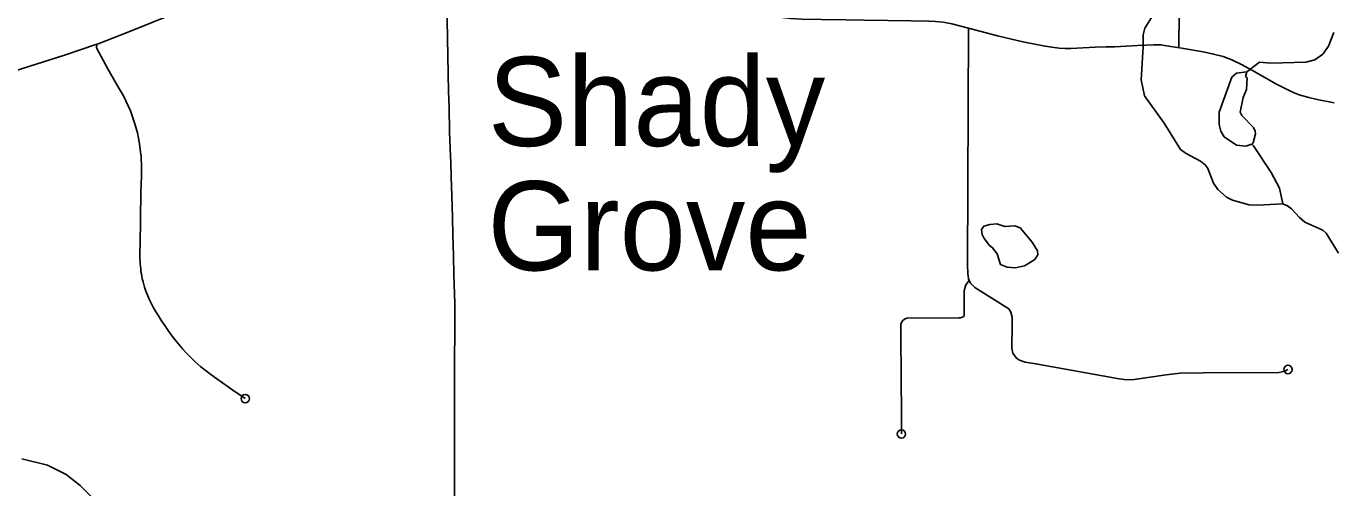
# Model space of a CAD drawing. Extents: x -19 to 366, y -4 to 359.
# Drawn here: x 143.314 to 144.78, y 191.501 to 192.02 of the extents above; entities that cross this region are included whole.
import ezdxf

# ---------------------------------------------------------------- set-up
doc = ezdxf.new("R2010")
doc.units = 0
for name, color, linetype in [('R_Horz Alg Annot', 7, 'Continuous'), ('R_ROW', 7, 'Continuous'), ('R_ROW Annot', 7, 'Continuous'), ('R_Temp Easement', 7, 'Continuous'), ('Sheet Fence', 7, 'Continuous')]:
    doc.layers.add(name, color=color, linetype=linetype)

msp = doc.modelspace()

# ---------------------------------------------------------------- linework, layer by layer
at = {"layer": 'R_ROW'}
for points in [[(143.785, 192.1059), (143.7855, 192.0918), (143.7865, 192.0521), (143.7867, 192.0267), (143.7881, 191.9466), (143.7888, 191.9291), (143.7894, 191.901)], [(143.4977, 192.041), (143.4828, 192.0352), (143.4289, 192.0136), (143.3943, 192.0002), (143.3929, 191.9996)], [(144.3723, 192.0176), (144.3536, 192.0224), (144.3441, 192.0243), (144.3355, 192.0253), (144.3281, 192.0257), (144.3077, 192.0261), (144.2556, 192.0267), (144.235, 192.0272), (144.2071, 192.0276), (144.1852, 192.0279), (144.1726, 192.0287), (144.1597, 192.0301), (144.1385, 192.0339), (144.126, 192.0374), (144.1074, 192.0433)], [(144.3723, 192.0176), (144.3714, 191.7521), (144.3715, 191.7421)], [(144.7833, 191.9338), (144.7642, 191.9375), (144.755, 191.9397), (144.7441, 191.9428), (144.7384, 191.9451), (144.7321, 191.948), (144.7186, 191.9549), (144.6915, 191.9702), (144.6833, 191.9747), (144.6799, 191.9765), (144.6682, 191.9822), (144.6585, 191.9857), (144.6478, 191.9885), (144.6379, 191.9908), (144.6143, 191.9947), (144.6071, 191.996), (144.5948, 191.998), (144.5885, 191.9989), (144.5803, 191.999), (144.5622, 191.9984), (144.5368, 191.9969), (144.527, 191.9967), (144.5149, 191.9963), (144.4873, 191.9949), (144.4811, 191.9949), (144.4743, 191.9953), (144.4659, 191.9962), (144.4584, 191.9974), (144.4353, 192.002), (144.4208, 192.0052), (144.4051, 192.009), (144.3723, 192.0176)], [(143.3929, 191.9996), (143.3568, 191.9872), (143.236, 191.9493)], [(143.3929, 191.9996), (143.3927, 191.9957), (143.4058, 191.9714), (143.4163, 191.9529), (143.4228, 191.9418), (143.4307, 191.9247), (143.4351, 191.9126), (143.4369, 191.9065), (143.4385, 191.9003), (143.4398, 191.8941), (143.4409, 191.8879), (143.4426, 191.8756), (143.4427, 191.8752), (143.4429, 191.8701), (143.443, 191.8649), (143.443, 191.8594), (143.443, 191.8519), (143.4428, 191.8421), (143.4426, 191.8331), (143.4415, 191.7741), (143.4414, 191.7669), (143.4414, 191.7611), (143.4414, 191.7581), (143.4415, 191.7558), (143.4417, 191.7526), (143.4419, 191.7505), (143.4423, 191.7474), (143.4426, 191.7445), (143.4431, 191.7418), (143.4436, 191.7384), (143.4441, 191.7364), (143.4449, 191.733), (143.4459, 191.7297), (143.4466, 191.727), (143.4482, 191.7223), (143.4502, 191.717), (143.4522, 191.7125), (143.4543, 191.708), (143.4566, 191.7037), (143.4588, 191.6999), (143.4622, 191.6946), (143.4658, 191.6892), (143.4695, 191.6837), (143.474, 191.6771), (143.4778, 191.6719), (143.4822, 191.6662), (143.4857, 191.6618), (143.4897, 191.6572), (143.4939, 191.6527), (143.4986, 191.6479), (143.5036, 191.6431), (143.5099, 191.6375), (143.5148, 191.6336), (143.521, 191.6289), (143.5279, 191.624), (143.5343, 191.6195), (143.5407, 191.615), (143.5458, 191.6114), (143.5598, 191.6017)], [(143.7894, 191.901), (143.7905, 191.8739), (143.7908, 191.8667), (143.7913, 191.8507), (143.7917, 191.8294), (143.7925, 191.8055), (143.7931, 191.7853), (143.7938, 191.7619), (143.7943, 191.7412), (143.7951, 191.7084), (143.7952, 191.673), (143.795, 191.6492), (143.7948, 191.6158), (143.7948, 191.6002), (143.7948, 191.5857), (143.7948, 191.5603), (143.7948, 191.5467), (143.7948, 191.4948), (143.7948, 191.4924)], [(144.3715, 191.7421), (144.3724, 191.7364), (144.3747, 191.7313), (144.3796, 191.7266), (144.4149, 191.7045), (144.4177, 191.7024), (144.4199, 191.6989), (144.4213, 191.6933), (144.4214, 191.6847), (144.4212, 191.6582), (144.4223, 191.6526), (144.4262, 191.647), (144.4296, 191.6448), (144.436, 191.6428), (144.4481, 191.6409), (144.5418, 191.6238), (144.5505, 191.6229), (144.5584, 191.6232), (144.5766, 191.6257), (144.5945, 191.6285), (144.6102, 191.6302), (144.6362, 191.6308), (144.7213, 191.6311), (144.728, 191.6325), (144.7314, 191.6344)], [(144.3733, 191.7343), (144.3694, 191.7294), (144.3676, 191.7228), (144.3676, 191.6988), (144.3676, 191.6961), (144.367, 191.6937), (144.3654, 191.6931), (144.3633, 191.6925), (144.3615, 191.6925), (144.3031, 191.6919), (144.3004, 191.691), (144.2983, 191.6892), (144.2964, 191.6858), (144.2964, 191.6816), (144.2964, 191.6719), (144.2973, 191.582), (144.297, 191.562)]]:
    msp.add_lwpolyline(points, dxfattribs=at)
for centre in [(144.7314, 191.6344), (143.5598, 191.6017), (144.297, 191.562)]:
    msp.add_circle(centre, 0.00473, dxfattribs=at)
at = {"layer": 'R_ROW Annot'}
msp.add_lwpolyline([(144.6088, 191.9957), (144.6097, 192.1166)], dxfattribs=at)
at = {"layer": 'R_Temp Easement'}
for points in [[(144.5922, 191.9109), (144.5702, 191.9416), (144.5666, 191.9598), (144.5687, 191.9968), (144.5688, 192.0102), (144.5704, 192.0177), (144.5798, 192.0325)], [(144.6853, 191.9687), (144.6994, 191.9795), (144.7121, 191.9784), (144.7515, 191.9795), (144.7617, 191.9823), (144.7704, 191.9886), (144.7771, 191.9976), (144.7829, 192.0128)], [(144.6906, 191.8874), (144.6921, 191.8889), (144.6948, 191.899), (144.6946, 191.9022), (144.6927, 191.9062), (144.6795, 191.9198), (144.6777, 191.9233), (144.681, 191.9397), (144.6847, 191.949), (144.6854, 191.9619), (144.6838, 191.9636), (144.6853, 191.9687), (144.6736, 191.9673), (144.6683, 191.9625), (144.6541, 191.9233), (144.654, 191.9095), (144.6558, 191.9021), (144.6598, 191.8957), (144.6735, 191.8865), (144.6841, 191.8851), (144.6906, 191.8874)], [(144.7883, 191.765), (144.7742, 191.7876), (144.7704, 191.791), (144.7504, 191.7997), (144.7443, 191.805), (144.7352, 191.815), (144.7308, 191.8183), (144.7256, 191.8206), (144.697, 191.819), (144.6876, 191.8195), (144.6689, 191.8247), (144.6623, 191.828), (144.6524, 191.8367), (144.6477, 191.8438), (144.6415, 191.8603), (144.6389, 191.8639), (144.6331, 191.8682), (144.617, 191.8769), (144.6105, 191.8816), (144.5922, 191.9109)], [(144.7256, 191.8206), (144.7217, 191.8382), (144.7126, 191.8557), (144.6925, 191.8855), (144.6906, 191.8874)], [(144.4439, 191.7773), (144.4305, 191.7936), (144.4244, 191.7957), (144.4132, 191.795), (144.4041, 191.798), (144.3965, 191.7972), (144.3895, 191.7952), (144.3869, 191.7918), (144.3879, 191.7861), (144.3899, 191.7814), (144.3962, 191.7738)], [(144.4439, 191.7773), (144.4499, 191.7676), (144.4503, 191.7631), (144.4469, 191.7579), (144.4392, 191.7529), (144.4352, 191.751), (144.425, 191.7487), (144.4159, 191.7493), (144.4085, 191.7523), (144.4046, 191.7642), (144.3994, 191.7712), (144.3962, 191.7738)], [(143.658, 191.3218), (143.6516, 191.3327), (143.6348, 191.351), (143.6296, 191.3604), (143.6278, 191.3671), (143.6415, 191.366), (143.6399, 191.3704), (143.6302, 191.3807), (143.6121, 191.3956), (143.603, 191.4127), (143.5938, 191.4206), (143.5634, 191.4373), (143.5233, 191.4506), (143.5039, 191.4538), (143.4851, 191.4628), (143.4556, 191.4739), (143.4097, 191.4834), (143.397, 191.4842), (143.3894, 191.4893), (143.3741, 191.504), (143.3584, 191.5167), (143.3377, 191.527), (143.3088, 191.5343)]]:
    msp.add_lwpolyline(points, dxfattribs=at)
at = {"layer": 'Sheet Fence'}
for points in [[(146.7783, 1.697), (146.5788, 10.3131), (146.3785, 18.9294), (146.1776, 27.5458), (145.9759, 36.1624), (145.7736, 44.7791), (145.5705, 53.396), (145.3668, 62.013), (145.1624, 70.6301), (144.9572, 79.2474), (144.7514, 87.8648), (144.5449, 96.4823), (144.3377, 105.1), (144.1299, 113.7179), (143.9213, 122.3359), (143.712, 130.954), (143.5021, 139.5723), (143.2915, 148.1907), (143.0802, 156.8092), (142.8682, 165.4279), (142.6555, 174.0468), (142.4422, 182.6658), (142.2282, 191.2849), (142.0135, 199.9042), (141.7981, 208.5236), (141.582, 217.1432), (141.3653, 225.7629), (141.1479, 234.3828), (140.9298, 243.0028), (140.711, 251.623), (140.4916, 260.2433), (140.2715, 268.8638), (140.0508, 277.4844), (139.8293, 286.1051), (139.6072, 294.726), (139.3845, 303.3471), (139.161, 311.9683), (138.937, 320.5896), (138.7122, 329.2111), (138.4868, 337.8328), (138.2607, 346.4546)], [(0, 189.5162), (7.1121, 189.5206), (14.2243, 189.5339), (21.3364, 189.556), (28.4484, 189.5869), (35.5605, 189.6267), (42.6725, 189.6754), (49.7844, 189.7329), (56.8962, 189.7992), (64.0079, 189.8744), (71.1196, 189.9584), (78.2311, 190.0512), (85.3425, 190.1529), (92.4538, 190.2635), (99.5649, 190.3829), (106.6759, 190.5111), (113.7867, 190.6482), (120.8974, 190.7941), (128.0078, 190.9489), (135.1181, 191.1125), (142.2282, 191.2849), (149.338, 191.4662), (156.4476, 191.6563), (163.5569, 191.8553), (170.666, 192.0631), (177.7749, 192.2798), (184.8835, 192.5053), (191.9917, 192.7396), (199.0997, 192.9828), (206.2074, 193.2348), (213.3147, 193.4956), (220.4218, 193.7653), (227.5285, 194.0438), (234.6348, 194.3312), (241.7408, 194.6274), (248.8464, 194.9324), (255.9516, 195.2463), (263.0564, 195.569), (270.1608, 195.9005), (277.2648, 196.2409), (284.3683, 196.5901), (291.4715, 196.9481), (298.5741, 197.315), (305.6763, 197.6907), (312.7781, 198.0753), (319.8793, 198.4686), (326.9801, 198.8708), (334.0804, 199.2818), (341.1801, 199.7017)]]:
    msp.add_spline(points, degree=3, dxfattribs=at)

# ---------------------------------------------------------------- texts
at = {"layer": 'R_Horz Alg Annot'}
for s, p in [('Shady', (143.8323, 191.8854)), ('Grove', (143.8319, 191.7458))]:
    msp.add_text(s, height=0.1, dxfattribs=at).set_placement(p)

doc.saveas('drawing.dxf')
